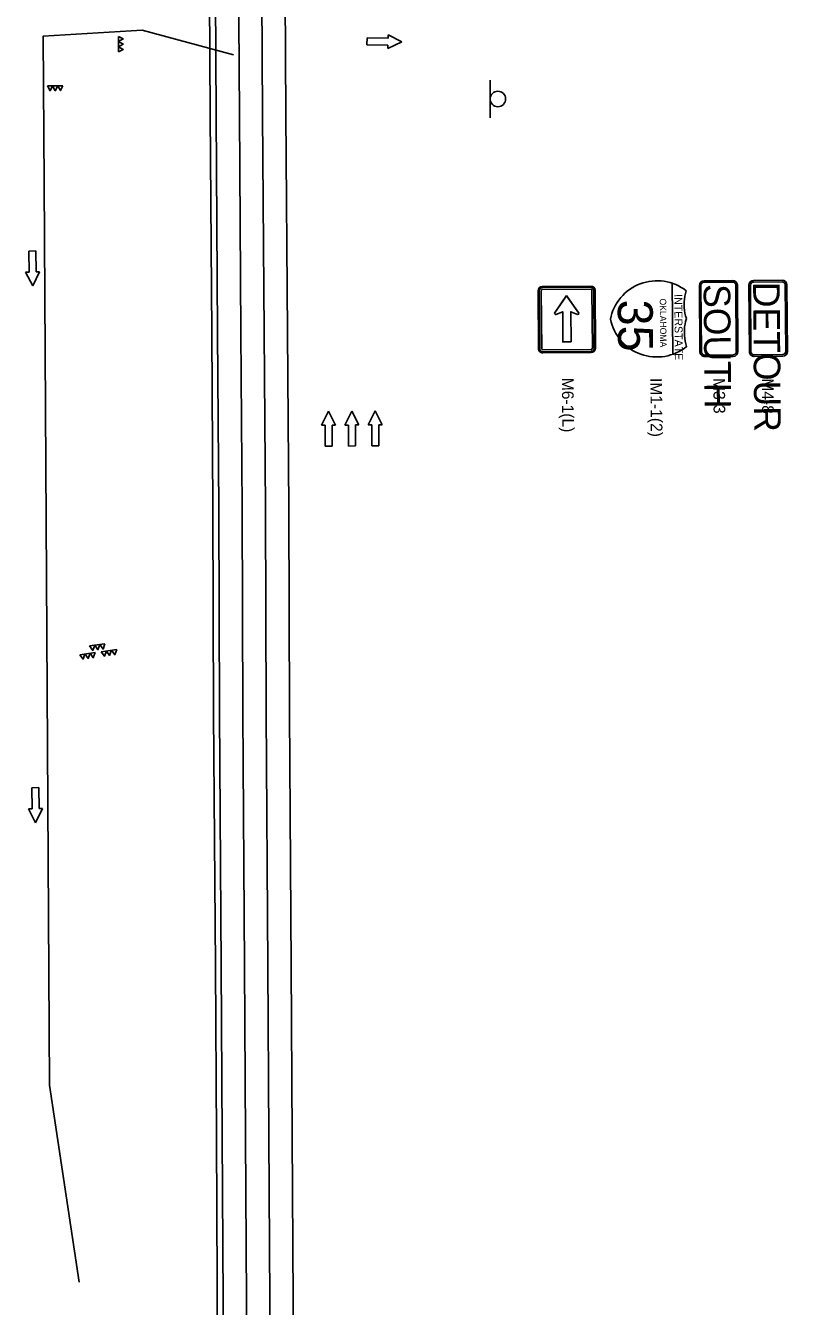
# Model space of a CAD drawing. Extents: x 2135767 to 2151731, y 141839 to 175894.
# Drawn here: x 2150671 to 2151063, y 144956 to 145614 of the extents above; entities that cross this region are included whole.
import ezdxf

# ---------------------------------------------------------------- set-up
doc = ezdxf.new("R2010")
doc.units = 0
for name, color, linetype in [('PR_Phasing_Detour_1', 7, 'Continuous'), ('PR_Phasing_Traffic_Barrier_Phase_1', 7, 'Continuous'), ('PR_Phasing_Traffic_Control_Devices_1', 7, 'Continuous'), ('PR_Phasing_Traffic_Striping_Dashed_Phase_1', 7, 'Continuous'), ('PR_Phasing_Traffic_Striping_White_Phase_1', 7, 'Continuous'), ('PR_Phasing_Traffic_Striping_Yellow_Phase_1', 7, 'Continuous'), ('Pr_Traffic_Arrows_Phase_1', 7, 'Continuous')]:
    doc.layers.add(name, color=color, linetype=linetype)

msp = doc.modelspace()

# ---------------------------------------------------------------- linework, layer by layer
at = {"layer": 'PR_Phasing_Detour_1'}
for p, q in [((2150909.88, 145586.33), (2150909.88, 145576.68)), ((2150909.88, 145576.68), (2150909.87, 145567.03)), ((2150934.57, 145478.05), (2150934.81, 145448.19)), ((2150935.18, 145478.05), (2150935.42, 145448.19)), ((2150935.18, 145478.05), (2150935.42, 145448.19)), ((2150936.44, 145448.2), (2150936.2, 145478.06)), ((2150936.44, 145448.2), (2150936.2, 145478.06)), ((2150961.69, 145480.43), (2150936.72, 145480.23)), ((2150961.7, 145479.82), (2150936.72, 145479.62)), ((2150961.7, 145479.82), (2150936.72, 145479.62)), ((2150936.73, 145478.6), (2150961.71, 145478.8)), ((2150936.73, 145478.6), (2150961.71, 145478.8)), ((2150962.25, 145478.27), (2150962.49, 145448.41)), ((2150962.25, 145478.27), (2150962.49, 145448.41)), ((2150963.51, 145448.42), (2150963.27, 145478.28)), ((2150963.51, 145448.42), (2150963.27, 145478.28)), ((2150964.12, 145448.43), (2150963.88, 145478.28)), ((2151003.64, 145482.18), (2151003.94, 145444.99)), ((2151017.58, 145480.73), (2151017.85, 145446.55)), ((2151018.39, 145480.74), (2151018.67, 145446.55)), ((2151034.65, 145483.31), (2151020, 145483.2)), ((2151034.66, 145482.5), (2151020.01, 145482.38)), ((2151036.57, 145446.7), (2151036.3, 145480.88)), ((2151037.39, 145446.7), (2151037.11, 145480.89)), ((2151043.03, 145480.87), (2151043.31, 145446.68)), ((2151043.85, 145480.87), (2151044.12, 145446.68)), ((2151060.11, 145483.44), (2151045.46, 145483.33)), ((2151060.11, 145482.63), (2151045.46, 145482.51)), ((2151062.03, 145446.83), (2151061.76, 145481.02)), ((2151062.84, 145446.84), (2151062.57, 145481.02)), ((2150949.25, 145475.48), (2150943.08, 145466.41)), ((2150955.56, 145466.51), (2150949.25, 145475.48)), ((2150943.78, 145465.72), (2150947.23, 145467.14)), ((2150947.23, 145467.14), (2150947.36, 145451.65)), ((2150951.52, 145451.69), (2150951.4, 145467.17)), ((2150951.4, 145467.17), (2150954.88, 145465.81)), ((2150947.36, 145451.65), (2150951.52, 145451.69)), ((2150961.96, 145447.87), (2150936.98, 145447.67)), ((2150961.96, 145447.87), (2150936.98, 145447.67)), ((2150936.99, 145446.65), (2150961.96, 145446.85)), ((2150936.99, 145446.65), (2150961.96, 145446.85)), ((2150936.99, 145446.04), (2150961.97, 145446.24)), ((2151020.31, 145444.94), (2151034.96, 145445.06)), ((2151020.31, 145444.12), (2151034.97, 145444.24)), ((2151045.76, 145445.07), (2151060.42, 145445.19)), ((2151045.77, 145444.26), (2151060.42, 145444.37))]:
    msp.add_line(p, q, dxfattribs=at)
for points in [[(2151010.74, 145478.01), (2151009.48, 145478.93), (2151008.17, 145479.76), (2151006.8, 145480.51), (2151005.39, 145481.17), (2151003.94, 145481.73), (2151002.46, 145482.21), (2151000.95, 145482.59), (2150999.42, 145482.87), (2150997.87, 145483.05), (2150996.32, 145483.14), (2150994.76, 145483.12), (2150993.21, 145483.01), (2150991.67, 145482.8), (2150990.14, 145482.49), (2150988.64, 145482.08), (2150987.16, 145481.58), (2150985.72, 145480.98), (2150984.33, 145480.3), (2150982.97, 145479.52), (2150981.67, 145478.67), (2150980.43, 145477.73), (2150979.25, 145476.71), (2150978.14, 145475.62), (2150977.1, 145474.47), (2150976.13, 145473.24), (2150975.25, 145471.96), (2150974.45, 145470.63), (2150973.73, 145469.25), (2150973.1, 145467.82), (2150972.57, 145466.36), (2150972.13, 145464.86), (2150971.79, 145463.34), (2150972.16, 145461.83), (2150972.62, 145460.34), (2150973.18, 145458.89), (2150973.83, 145457.48), (2150974.56, 145456.1), (2150975.39, 145454.78), (2150976.29, 145453.52), (2150977.28, 145452.31), (2150978.34, 145451.17), (2150979.47, 145450.1), (2150980.66, 145449.1), (2150981.92, 145448.18), (2150983.23, 145447.35), (2150984.6, 145446.59), (2150986.01, 145445.93), (2150987.45, 145445.36), (2150988.94, 145444.88), (2150990.45, 145444.5), (2150991.98, 145444.21), (2150993.52, 145444.03), (2150995.08, 145443.94), (2150996.63, 145443.95), (2150998.19, 145444.06), (2150999.73, 145444.27), (2151001.26, 145444.57), (2151002.76, 145444.98), (2151004.23, 145445.47), (2151005.68, 145446.06), (2151007.08, 145446.75), (2151008.43, 145447.52), (2151009.73, 145448.37), (2151010.98, 145449.3), (2151010.58, 145450.71), (2151010.26, 145452.13), (2151010.04, 145453.57), (2151009.89, 145455.02), (2151009.84, 145456.47), (2151009.87, 145457.93), (2151009.99, 145459.38), (2151010.19, 145460.82), (2151010.48, 145462.25), (2151010.86, 145463.66), (2151010.46, 145465.06), (2151010.15, 145466.48), (2151009.92, 145467.92), (2151009.78, 145469.37), (2151009.72, 145470.83), (2151009.76, 145472.28), (2151009.87, 145473.74), (2151010.08, 145475.18), (2151010.37, 145476.6), (2151010.74, 145478.01)], [(2150949.25, 145475.53), (2150943.07, 145466.46)], [(2150955.56, 145466.56), (2150949.25, 145475.53)], [(2150943.77, 145465.78), (2150947.23, 145467.19), (2150947.36, 145451.71), (2150951.52, 145451.74), (2150951.39, 145467.22), (2150954.87, 145465.86)]]:
    msp.add_lwpolyline(points, dxfattribs=at)
msp.add_circle((2150913.88, 145576.68), 4, dxfattribs=at)
for centre, radius, start, end in [((2150936.74, 145478.07), 2.16, 90.46107, 180.46107), ((2150936.74, 145478.07), 1.55, 90.46107, 180.46107), ((2150936.74, 145478.07), 1.55, 90.46107, 180.46107), ((2150936.74, 145478.07), 0.537, 90.46107, 180.46107), ((2150936.74, 145478.07), 0.537, 90.46107, 180.46107), ((2150961.71, 145478.27), 2.16, 0.46107, 90.46107), ((2150961.71, 145478.27), 1.55, 0.46107, 90.46107), ((2150961.71, 145478.27), 1.55, 0.46107, 90.46107), ((2150961.71, 145478.27), 0.537, 0.46107, 90.46107), ((2150961.71, 145478.27), 0.537, 0.46107, 90.46107), ((2151020.02, 145480.75), 2.44, 90.46107, 180.46107), ((2151020.02, 145480.75), 1.63, 90.46107, 180.46107), ((2151034.67, 145480.87), 2.44, 0.46107, 90.46107), ((2151034.67, 145480.87), 1.63, 0.46107, 90.46107), ((2151045.48, 145480.88), 2.44, 90.46107, 180.46107), ((2151045.48, 145480.88), 1.63, 90.46107, 180.46107), ((2151060.13, 145481), 2.44, 0.46107, 90.46107), ((2151060.13, 145481), 1.63, 0.46107, 90.46107), ((2150943.77, 145466.47), 0.694, 180.46107, 270.46107), ((2150943.77, 145466.42), 0.694, 180.46107, 270.46107), ((2150954.87, 145466.56), 0.694, 270.46107, 0.46107), ((2150954.87, 145466.51), 0.694, 270.46107, 0.46107), ((2150936.98, 145448.21), 2.16, 180.46107, 270.46107), ((2150936.98, 145448.21), 1.55, 180.46107, 270.46107), ((2150936.98, 145448.21), 1.55, 180.46107, 270.46107), ((2150936.98, 145448.21), 0.537, 180.46107, 270.46107), ((2150936.98, 145448.21), 0.537, 180.46107, 270.46107), ((2150961.95, 145448.41), 1.55, 270.46107, 0.46107), ((2150961.95, 145448.41), 1.55, 270.46107, 0.46107), ((2150961.95, 145448.41), 0.537, 270.46107, 0.46107), ((2150961.95, 145448.41), 0.537, 270.46107, 0.46107), ((2150961.95, 145448.41), 2.16, 270.46107, 0.46107), ((2151020.29, 145446.57), 2.44, 180.46107, 270.46107), ((2151020.29, 145446.57), 1.63, 180.46107, 270.46107), ((2151034.95, 145446.68), 1.63, 270.46107, 0.46107), ((2151034.95, 145446.68), 2.44, 270.46107, 0.46107), ((2151045.75, 145446.7), 2.44, 180.46107, 270.46107), ((2151045.75, 145446.7), 1.63, 180.46107, 270.46107), ((2151060.4, 145446.82), 2.44, 270.46107, 0.46107), ((2151060.4, 145446.82), 1.63, 270.46107, 0.46107)]:
    msp.add_arc(centre, radius, start, end, dxfattribs=at)
at = {"layer": 'PR_Phasing_Traffic_Barrier_Phase_1'}
msp.add_lwpolyline([(2150765.18, 145690.17), (2150765.87, 145568.57), (2150766.69, 145456.49), (2150767.25, 145365.88), (2150767.65, 145260.61), (2150768.52, 145130.54), (2150769.07, 145042.71), (2150769.65, 144930.44), (2150770.69, 144766.95), (2150771.26, 144659.72), (2150771.35, 144642.77), (2150771.7, 144580.84)], dxfattribs=at)
at = {"layer": 'PR_Phasing_Traffic_Control_Devices_1'}
for p, q in [((2150718.64, 145600.88), (2150718.64, 145608.88)), ((2150682.14, 145583.42), (2150690.14, 145583.47)), ((2150703.83, 145295.27), (2150711.75, 145296.36)), ((2150709.84, 145292.31), (2150717.77, 145293.4)), ((2150698.79, 145290.79), (2150706.72, 145291.88))]:
    msp.add_line(p, q, dxfattribs=at)
for points in [[(2150777.94, 145599.42), (2150730.93, 145612), (2150679.99, 145609.03), (2150680.43, 145533.37), (2150683.12, 145069.39), (2150698.53, 144968)], [(2150718.64, 145600.88), (2150721.14, 145602.21), (2150718.64, 145603.55), (2150721.14, 145604.88), (2150718.64, 145606.21), (2150721.14, 145607.55), (2150718.64, 145608.88)], [(2150682.14, 145583.42), (2150683.49, 145580.93), (2150684.8, 145583.44), (2150686.15, 145580.94), (2150687.47, 145583.45), (2150688.82, 145580.96), (2150690.14, 145583.47)], [(2150703.83, 145295.27), (2150705.49, 145292.97), (2150706.47, 145295.63), (2150708.13, 145293.33), (2150709.11, 145295.99), (2150710.77, 145293.7), (2150711.75, 145296.36)], [(2150709.84, 145292.31), (2150711.5, 145290.01), (2150712.48, 145292.67), (2150714.15, 145290.38), (2150715.13, 145293.04), (2150716.79, 145290.74), (2150717.77, 145293.4)], [(2150698.79, 145290.79), (2150700.45, 145288.49), (2150701.43, 145291.15), (2150703.1, 145288.86), (2150704.08, 145291.51), (2150705.74, 145289.22), (2150706.72, 145291.88)]]:
    msp.add_lwpolyline(points, dxfattribs=at)
at = {"layer": 'PR_Phasing_Traffic_Striping_Dashed_Phase_1'}
for points in [[(2150780.18, 145690.3), (2150780.87, 145568.67), (2150781.69, 145456.59), (2150782.25, 145365.95), (2150782.65, 145260.69), (2150783.52, 145130.64), (2150784.07, 145042.8), (2150784.65, 144930.53), (2150785.69, 144767.03), (2150786.17, 144667.55), (2150786.79, 144583.05)], [(2150792.18, 145690.37), (2150792.87, 145568.75), (2150793.69, 145456.67), (2150794.25, 145366.01), (2150794.65, 145260.76), (2150795.52, 145130.72), (2150796.07, 145042.87), (2150796.65, 144930.6), (2150797.69, 144767.1), (2150798.17, 144667.62), (2150798.79, 144582.71)]]:
    msp.add_lwpolyline(points, dxfattribs=at)
at = {"layer": 'PR_Phasing_Traffic_Striping_White_Phase_1'}
msp.add_lwpolyline([(2150768.18, 145690.19), (2150768.87, 145568.59), (2150769.69, 145456.51), (2150770.25, 145365.89), (2150770.65, 145260.63), (2150771.52, 145130.56), (2150772.07, 145042.73), (2150772.65, 144930.46), (2150773.69, 144766.97), (2150774.17, 144667.47), (2150774.79, 144582.12)], dxfattribs=at)
at = {"layer": 'PR_Phasing_Traffic_Striping_Yellow_Phase_1'}
msp.add_lwpolyline([(2150804.18, 145690.44), (2150804.87, 145568.83), (2150805.69, 145456.75), (2150806.25, 145366.07), (2150806.65, 145260.82), (2150807.52, 145130.8), (2150808.07, 145042.94), (2150808.65, 144930.67), (2150809.69, 144767.17), (2150810.17, 144667.69), (2150810.51, 144576.41)], dxfattribs=at)
at = {"layer": 'Pr_Traffic_Arrows_Phase_1'}
for p, q in [((2150857.37, 145607.96), (2150857.4, 145609.76)), ((2150857.4, 145609.76), (2150864.53, 145606.03)), ((2150846.5, 145604.56), (2150846.57, 145608.16)), ((2150857.3, 145604.36), (2150846.5, 145604.56)), ((2150846.57, 145608.16), (2150857.37, 145607.96)), ((2150864.53, 145606.03), (2150857.27, 145602.56)), ((2150857.27, 145602.56), (2150857.3, 145604.36)), ((2150672.64, 145498.46), (2150676.24, 145498.48)), ((2150672.71, 145487.66), (2150672.64, 145498.46)), ((2150676.24, 145498.48), (2150676.31, 145487.68)), ((2150670.91, 145487.65), (2150672.71, 145487.66)), ((2150674.55, 145480.47), (2150670.91, 145487.65)), ((2150678.11, 145487.69), (2150674.55, 145480.47)), ((2150676.31, 145487.68), (2150678.11, 145487.69)), ((2150823.18, 145408.85), (2150826.73, 145416.07)), ((2150826.73, 145416.07), (2150830.38, 145408.89)), ((2150835.18, 145408.92), (2150838.73, 145416.15)), ((2150838.73, 145416.15), (2150842.38, 145408.97)), ((2150847.18, 145409), (2150850.73, 145416.23)), ((2150850.73, 145416.23), (2150854.38, 145409.05)), ((2150824.98, 145408.86), (2150823.18, 145408.85)), ((2150825.05, 145398.06), (2150824.98, 145408.86)), ((2150830.38, 145408.89), (2150828.58, 145408.88)), ((2150828.58, 145408.88), (2150828.65, 145398.08)), ((2150836.98, 145408.94), (2150835.18, 145408.92)), ((2150837.05, 145398.14), (2150836.98, 145408.94)), ((2150842.38, 145408.97), (2150840.58, 145408.96)), ((2150840.58, 145408.96), (2150840.65, 145398.16)), ((2150848.98, 145409.01), (2150847.18, 145409)), ((2150849.05, 145398.22), (2150848.98, 145409.01)), ((2150854.38, 145409.05), (2150852.58, 145409.04)), ((2150852.58, 145409.04), (2150852.65, 145398.24)), ((2150828.65, 145398.08), (2150825.05, 145398.06)), ((2150840.65, 145398.16), (2150837.05, 145398.14)), ((2150852.65, 145398.24), (2150849.05, 145398.22)), ((2150674.12, 145222.35), (2150677.72, 145222.38)), ((2150674.21, 145211.55), (2150674.12, 145222.35)), ((2150677.72, 145222.38), (2150677.81, 145211.58)), ((2150672.41, 145211.53), (2150674.21, 145211.55)), ((2150676.07, 145204.37), (2150672.41, 145211.53)), ((2150679.61, 145211.6), (2150676.07, 145204.37)), ((2150677.81, 145211.58), (2150679.61, 145211.6))]:
    msp.add_line(p, q, dxfattribs=at)

# ---------------------------------------------------------------- texts
at = {"layer": 'PR_Phasing_Detour_1'}
for s, height, p in [('SOUTH', 13.675, (2151019.74, 145481.39)), ('DETOUR', 13.675, (2151045.19, 145482.56)), ('35', 17.974, (2150975.55, 145473.41)), ('OKLAHOMA', 3.31, (2150997.18, 145474.01)), ('INTERSTATE', 4.084, (2151004.68, 145476.24)), ('M6-1(L)', 6, (2150946.81, 145433.23)), ('IM1-1(2)', 6, (2150992.35, 145433.12)), ('M3-3', 6, (2151024.73, 145433.07)), ('M4-8', 6, (2151049.71, 145432.95))]:
    msp.add_text(s, height=height, rotation=270.46107, dxfattribs=at).set_placement(p)

doc.saveas('drawing.dxf')
